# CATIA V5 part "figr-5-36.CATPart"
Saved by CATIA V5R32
Part number: Part1
Bounding box of the stored display mesh (mm): x -80 to 80, y -60 to 60, z 0 to 120
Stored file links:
  D:\PROJECTS\Project 2022\CATIA V5 6R 2022\Resources\Part Files\c05_catia_v5_6r2022_prt\figr-5-36.CATPart
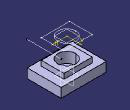
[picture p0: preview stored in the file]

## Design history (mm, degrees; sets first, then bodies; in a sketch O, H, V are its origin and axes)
Set1
  Plane1: type Offset, RefPlane xy-plane, Offset 120
Body1 (main body)
  Sketch1 on xy-plane, origin (0, 0, 0), H (1, 0, 0), V (0, 1, 0)
    line L1 (80, 60) -> (80, -60)
    line L2 (80, -60) -> (-80, -60)
    line L3 (-80, -60) -> (-80, 60)
    line L4 (-80, 60) -> (80, 60)
    circle A1 centre (0, 0) radius 31.6228
    line L5 (50, 40) -> (50, -40)
    line L6 (50, -40) -> (-50, -40)
    line L7 (-50, -40) -> (-50, 40)
    line L8 (-50, 40) -> (50, 40)
    vertical: L1 V, L3 V, L5 V, L7 V
    horizontal: L2 H, L4 H, L6 H, L8 H
    equidistance: L1 L3 O, L2 L4 O, L5 L7 O, L6 L8 O
  MultiPad1: profile Sketch1, domains (length 51; length 33; length 14)
  Sketch2 on Plane1, origin (0, 0, 120), H (1, 0, 0), V (0, 1, 0)
    projected line E1 (50, 40) -> (-50, 40) from edge [face of MultiPad1 | face of MultiPad1]
    projected line E2 (-50, 40) -> (-50, -40) from edge [face of MultiPad1 | face of MultiPad1]
    projected line E3 (-50, -40) -> (50, -40) from edge [face of MultiPad1 | face of MultiPad1]
    projected line E4 (50, -40) -> (50, 40) from edge [face of MultiPad1 | face of MultiPad1]
    projected circle E5 centre (0, 0) radius 31.6228 from edge [face of MultiPad1 | face of MultiPad1]
    projected line E6 (80, -60) -> (80, 60) from edge [face of MultiPad1 | face of MultiPad1]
